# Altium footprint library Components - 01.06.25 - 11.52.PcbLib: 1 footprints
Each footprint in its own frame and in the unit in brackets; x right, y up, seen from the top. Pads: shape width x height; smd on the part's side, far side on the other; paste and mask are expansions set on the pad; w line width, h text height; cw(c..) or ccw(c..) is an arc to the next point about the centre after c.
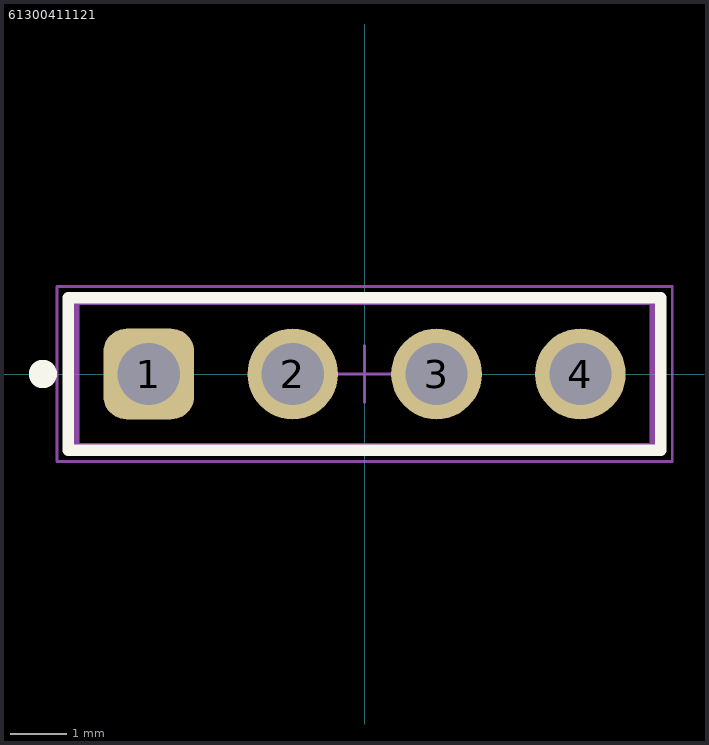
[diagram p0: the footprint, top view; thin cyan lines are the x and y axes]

## 61300411121 [mm] "Pin Header, pitch 2.54 mm, THT, Vertical, single row, 4p"
height 8.54
pads (4):
  rrect50% 1.6x1.6 hole 1.1: 1(-3.81,0)
  round 1.6 hole 1.1: 2(-1.27,0) 3(1.27,0) 4(3.81,0)
Top Overlay:
  circle w0.25: c-5.68,0 r0.125
  lines w0.2: -5.23,-1.345 5.23,-1.345 5.23,1.345 -5.23,1.345 -5.23,-1.345
Top Designator:
  text ".Designator" at -7.498,-0.5 h1.5
Top Component Outline:
  lines w0.1: -5.08,-1.27 -5.08,1.27 5.08,1.27 5.08,-1.27 -5.08,-1.27
Top Courtyard:
  lines w0.05: -5.43,-1.545 -5.43,1.545 5.43,1.545 5.43,-1.545 -5.43,-1.545
Top Component Center:
  lines w0.05: -0.5,0 0.5,0 ; 0,-0.5 0,0.5
3D body "61300411121.stp": height 8.57, standoff -2.97, extent -5.08,-1.27 5.08,1.27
